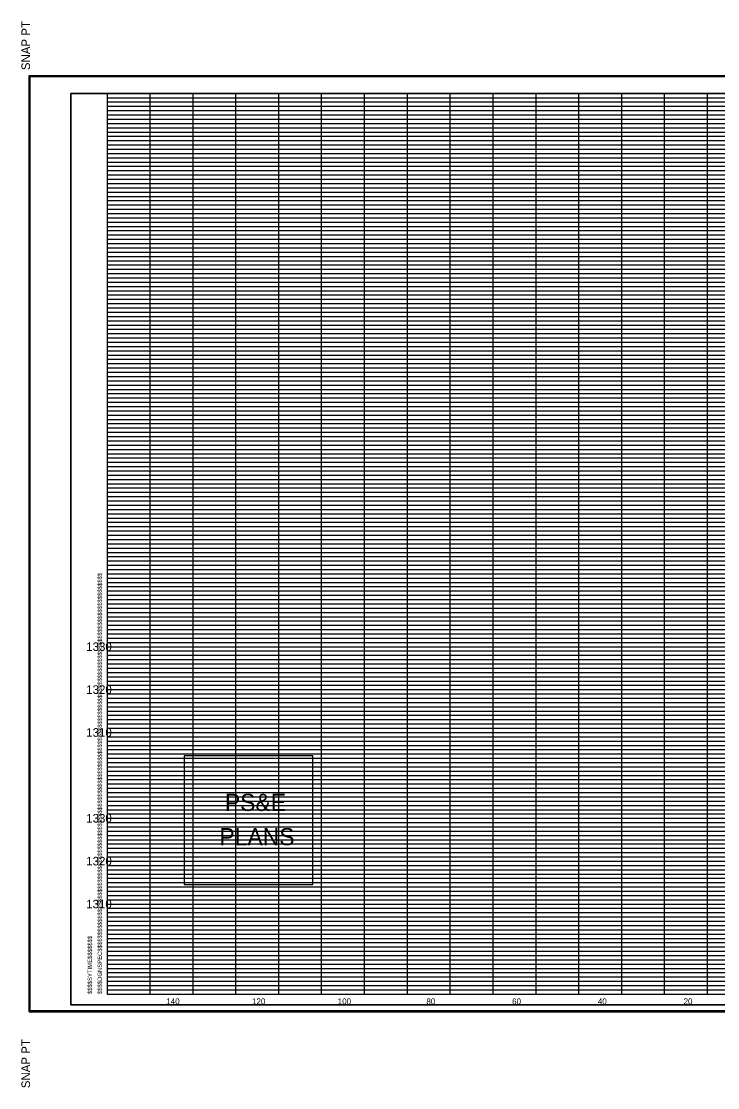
# Model space of a CAD drawing. Extents: x 980 to 1324, y 978 to 1497.
# Drawn here: x 979.9 to 1142.4, y 1248.2 to 1496.8 of the extents above; entities that cross this region are included whole.
import ezdxf

# ---------------------------------------------------------------- set-up
doc = ezdxf.new("R2010")
doc.units = 0
for name, color, linetype in [('DESIGN - SHEET - Corner Text', 7, 'Continuous'), ('DESIGN - SHEET - Light Grid', 7, 'Continuous'), ('DESIGN - SHEET - Linework', 7, 'Continuous'), ('DESIGN - SHEET - Plot Shape', 7, 'Continuous'), ('DESIGN - TYPICAL - Finished Grade and Subgrade', 7, 'Continuous'), ('DESIGN - TYPICAL - Text', 7, 'Continuous')]:
    doc.layers.add(name, color=color, linetype=linetype)

# ---------------------------------------------------------------- blocks, each defined once
blk = doc.blocks.new('XSTSHT')
at = {"layer": 'DESIGN - SHEET - Light Grid'}
for p, q in [((0, 20.9), (8, 20.9)), ((8, 20.9), (16, 20.9)), ((0, 20.8), (8, 20.8)), ((0, 20.7), (8, 20.7)), ((8, 20.8), (16, 20.8)), ((8, 20.7), (16, 20.7)), ((0, 20.6), (8, 20.6)), ((0, 20.5), (8, 20.5)), ((0, 20.4), (8, 20.4)), ((8, 20.6), (16, 20.6)), ((8, 20.5), (16, 20.5)), ((8, 20.4), (16, 20.4)), ((0, 20.3), (8, 20.3)), ((0, 20.2), (8, 20.2)), ((8, 20.3), (16, 20.3)), ((8, 20.2), (16, 20.2)), ((0, 20.1), (8, 20.1)), ((0, 19.9), (8, 19.9)), ((8, 20.1), (16, 20.1)), ((8, 19.9), (16, 19.9)), ((0, 19.8), (8, 19.8)), ((0, 19.7), (8, 19.7)), ((8, 19.8), (16, 19.8)), ((8, 19.7), (16, 19.7)), ((0, 19.6), (8, 19.6)), ((0, 19.5), (8, 19.5)), ((0, 19.4), (8, 19.4)), ((8, 19.6), (16, 19.6)), ((8, 19.5), (16, 19.5)), ((8, 19.4), (16, 19.4)), ((0, 19.3), (8, 19.3)), ((0, 19.2), (8, 19.2)), ((8, 19.3), (16, 19.3)), ((8, 19.2), (16, 19.2)), ((0, 19.1), (8, 19.1)), ((0, 18.9), (8, 18.9)), ((8, 19.1), (16, 19.1)), ((8, 18.9), (16, 18.9)), ((0, 18.8), (8, 18.8)), ((0, 18.7), (8, 18.7)), ((8, 18.8), (16, 18.8)), ((8, 18.7), (16, 18.7)), ((0, 18.6), (8, 18.6)), ((0, 18.5), (8, 18.5)), ((0, 18.4), (8, 18.4)), ((8, 18.6), (16, 18.6)), ((8, 18.5), (16, 18.5)), ((8, 18.4), (16, 18.4)), ((0, 18.3), (8, 18.3)), ((0, 18.2), (8, 18.2)), ((8, 18.3), (16, 18.3)), ((8, 18.2), (16, 18.2)), ((0, 18.1), (8, 18.1)), ((8, 18.1), (16, 18.1)), ((0, 17.9), (8, 17.9)), ((0, 17.8), (8, 17.8)), ((0, 17.7), (8, 17.7)), ((8, 17.9), (16, 17.9)), ((8, 17.8), (16, 17.8)), ((8, 17.7), (16, 17.7)), ((0, 17.6), (8, 17.6)), ((0, 17.5), (8, 17.5)), ((8, 17.6), (16, 17.6)), ((8, 17.5), (16, 17.5)), ((0, 17.4), (8, 17.4)), ((0, 17.3), (8, 17.3)), ((0, 17.2), (8, 17.2)), ((8, 17.4), (16, 17.4)), ((8, 17.3), (16, 17.3)), ((8, 17.2), (16, 17.2)), ((0, 17.1), (8, 17.1)), ((8, 17.1), (16, 17.1)), ((0, 16.9), (8, 16.9)), ((0, 16.8), (8, 16.8)), ((0, 16.7), (8, 16.7)), ((8, 16.9), (16, 16.9)), ((8, 16.8), (16, 16.8)), ((8, 16.7), (16, 16.7)), ((0, 16.6), (8, 16.6)), ((0, 16.5), (8, 16.5)), ((8, 16.6), (16, 16.6)), ((8, 16.5), (16, 16.5)), ((0, 16.4), (8, 16.4)), ((0, 16.3), (8, 16.3)), ((0, 16.2), (8, 16.2)), ((8, 16.4), (16, 16.4)), ((8, 16.3), (16, 16.3)), ((8, 16.2), (16, 16.2)), ((0, 16.1), (8, 16.1)), ((8, 16.1), (16, 16.1)), ((0, 15.9), (8, 15.9)), ((0, 15.8), (8, 15.8)), ((0, 15.7), (8, 15.7)), ((8, 15.9), (16, 15.9)), ((8, 15.8), (16, 15.8)), ((8, 15.7), (16, 15.7)), ((0, 15.6), (8, 15.6)), ((0, 15.5), (8, 15.5)), ((8, 15.6), (16, 15.6)), ((8, 15.5), (16, 15.5)), ((0, 15.4), (8, 15.4)), ((0, 15.3), (8, 15.3)), ((0, 15.2), (8, 15.2)), ((8, 15.4), (16, 15.4)), ((8, 15.3), (16, 15.3)), ((8, 15.2), (16, 15.2)), ((0, 15.1), (8, 15.1)), ((8, 15.1), (16, 15.1)), ((0, 14.9), (8, 14.9)), ((0, 14.8), (8, 14.8)), ((0, 14.7), (8, 14.7)), ((8, 14.9), (16, 14.9)), ((8, 14.8), (16, 14.8)), ((8, 14.7), (16, 14.7)), ((0, 14.6), (8, 14.6)), ((0, 14.5), (8, 14.5)), ((8, 14.6), (16, 14.6)), ((8, 14.5), (16, 14.5)), ((0, 14.4), (8, 14.4)), ((0, 14.3), (8, 14.3)), ((0, 14.2), (8, 14.2)), ((8, 14.4), (16, 14.4)), ((8, 14.3), (16, 14.3)), ((8, 14.2), (16, 14.2)), ((0, 14.1), (8, 14.1)), ((8, 14.1), (16, 14.1)), ((0, 13.9), (8, 13.9)), ((0, 13.8), (8, 13.8)), ((0, 13.7), (8, 13.7)), ((8, 13.9), (16, 13.9)), ((8, 13.8), (16, 13.8)), ((8, 13.7), (16, 13.7)), ((0, 13.6), (8, 13.6)), ((0, 13.5), (8, 13.5)), ((8, 13.6), (16, 13.6)), ((8, 13.5), (16, 13.5)), ((0, 13.4), (8, 13.4)), ((0, 13.3), (8, 13.3)), ((0, 13.2), (8, 13.2)), ((8, 13.4), (16, 13.4)), ((8, 13.3), (16, 13.3)), ((8, 13.2), (16, 13.2)), ((0, 13.1), (8, 13.1)), ((8, 13.1), (16, 13.1)), ((0, 12.9), (8, 12.9)), ((0, 12.8), (8, 12.8)), ((0, 12.7), (8, 12.7)), ((8, 12.9), (16, 12.9)), ((8, 12.8), (16, 12.8)), ((8, 12.7), (16, 12.7)), ((0, 12.6), (8, 12.6)), ((0, 12.5), (8, 12.5)), ((8, 12.6), (16, 12.6)), ((8, 12.5), (16, 12.5)), ((0, 12.4), (8, 12.4)), ((0, 12.3), (8, 12.3)), ((0, 12.2), (8, 12.2)), ((8, 12.4), (16, 12.4)), ((8, 12.3), (16, 12.3)), ((8, 12.2), (16, 12.2)), ((0, 12.1), (8, 12.1)), ((8, 12.1), (16, 12.1)), ((0, 11.9), (8, 11.9)), ((0, 11.8), (8, 11.8)), ((0, 11.7), (8, 11.7)), ((8, 11.9), (16, 11.9)), ((8, 11.8), (16, 11.8)), ((8, 11.7), (16, 11.7)), ((0, 11.6), (8, 11.6)), ((0, 11.5), (8, 11.5)), ((8, 11.6), (16, 11.6)), ((8, 11.5), (16, 11.5)), ((0, 11.4), (8, 11.4)), ((0, 11.3), (8, 11.3)), ((0, 11.2), (8, 11.2)), ((8, 11.4), (16, 11.4)), ((8, 11.3), (16, 11.3)), ((8, 11.2), (16, 11.2)), ((0, 11.1), (8, 11.1)), ((8, 11.1), (16, 11.1)), ((0, 10.9), (8, 10.9)), ((0, 10.8), (8, 10.8)), ((0, 10.7), (8, 10.7)), ((8, 10.9), (16, 10.9)), ((8, 10.8), (16, 10.8)), ((8, 10.7), (16, 10.7)), ((0, 10.6), (8, 10.6)), ((0, 10.5), (8, 10.5)), ((8, 10.6), (16, 10.6)), ((8, 10.5), (16, 10.5)), ((0, 10.4), (8, 10.4)), ((0, 10.3), (8, 10.3)), ((0, 10.2), (8, 10.2)), ((8, 10.4), (16, 10.4)), ((8, 10.3), (16, 10.3)), ((8, 10.2), (16, 10.2)), ((0, 10.1), (8, 10.1)), ((8, 10.1), (16, 10.1)), ((0, 9.9), (8, 9.9)), ((0, 9.8), (8, 9.8)), ((0, 9.7), (8, 9.7)), ((8, 9.9), (16, 9.9)), ((8, 9.8), (16, 9.8)), ((8, 9.7), (16, 9.7)), ((0, 9.6), (8, 9.6)), ((0, 9.5), (8, 9.5)), ((8, 9.6), (16, 9.6)), ((8, 9.5), (16, 9.5)), ((0, 9.4), (8, 9.4)), ((0, 9.3), (8, 9.3)), ((0, 9.2), (8, 9.2)), ((8, 9.4), (16, 9.4)), ((8, 9.3), (16, 9.3)), ((8, 9.2), (16, 9.2)), ((0, 9.1), (8, 9.1)), ((8, 9.1), (16, 9.1)), ((0, 8.9), (8, 8.9)), ((0, 8.8), (8, 8.8)), ((8, 8.9), (16, 8.9)), ((8, 8.8), (16, 8.8)), ((0, 8.7), (8, 8.7)), ((0, 8.6), (8, 8.6)), ((0, 8.5), (8, 8.5)), ((8, 8.7), (16, 8.7)), ((8, 8.6), (16, 8.6)), ((8, 8.5), (16, 8.5)), ((0, 8.4), (8, 8.4)), ((0, 8.3), (8, 8.3)), ((8, 8.4), (16, 8.4)), ((8, 8.3), (16, 8.3)), ((0, 8.2), (8, 8.2)), ((0, 8.1), (8, 8.1)), ((8, 8.2), (16, 8.2)), ((8, 8.1), (16, 8.1)), ((0, 7.9), (8, 7.9)), ((0, 7.8), (8, 7.8)), ((8, 7.9), (16, 7.9)), ((8, 7.8), (16, 7.8)), ((0, 7.7), (8, 7.7)), ((0, 7.6), (8, 7.6)), ((0, 7.5), (8, 7.5)), ((8, 7.7), (16, 7.7)), ((8, 7.6), (16, 7.6)), ((8, 7.5), (16, 7.5)), ((0, 7.4), (8, 7.4)), ((0, 7.3), (8, 7.3)), ((8, 7.4), (16, 7.4)), ((8, 7.3), (16, 7.3)), ((0, 7.2), (8, 7.2)), ((0, 7.1), (8, 7.1)), ((8, 7.2), (16, 7.2)), ((8, 7.1), (16, 7.1)), ((0, 6.9), (8, 6.9)), ((0, 6.8), (8, 6.8)), ((8, 6.9), (16, 6.9)), ((8, 6.8), (16, 6.8)), ((0, 6.7), (8, 6.7)), ((0, 6.6), (8, 6.6)), ((0, 6.5), (8, 6.5)), ((8, 6.7), (16, 6.7)), ((8, 6.6), (16, 6.6)), ((8, 6.5), (16, 6.5)), ((0, 6.4), (8, 6.4)), ((0, 6.3), (8, 6.3)), ((8, 6.4), (16, 6.4)), ((8, 6.3), (16, 6.3)), ((0, 6.2), (8, 6.2)), ((0, 6.1), (8, 6.1)), ((8, 6.2), (16, 6.2)), ((8, 6.1), (16, 6.1)), ((0, 5.9), (8, 5.9)), ((0, 5.8), (8, 5.8)), ((8, 5.9), (16, 5.9)), ((8, 5.8), (16, 5.8)), ((0, 5.7), (8, 5.7)), ((0, 5.6), (8, 5.6)), ((0, 5.5), (8, 5.5)), ((8, 5.7), (16, 5.7)), ((8, 5.6), (16, 5.6)), ((8, 5.5), (16, 5.5)), ((0, 5.4), (8, 5.4)), ((0, 5.3), (8, 5.3)), ((8, 5.4), (16, 5.4)), ((8, 5.3), (16, 5.3)), ((0, 5.2), (8, 5.2)), ((0, 5.1), (8, 5.1)), ((8, 5.2), (16, 5.2)), ((8, 5.1), (16, 5.1)), ((0, 4.9), (8, 4.9)), ((0, 4.8), (8, 4.8)), ((8, 4.9), (16, 4.9)), ((8, 4.8), (16, 4.8)), ((0, 4.7), (8, 4.7)), ((0, 4.6), (8, 4.6)), ((0, 4.5), (8, 4.5)), ((8, 4.7), (16, 4.7)), ((8, 4.6), (16, 4.6)), ((8, 4.5), (16, 4.5)), ((0, 4.4), (8, 4.4)), ((0, 4.3), (8, 4.3)), ((8, 4.4), (16, 4.4)), ((8, 4.3), (16, 4.3)), ((0, 4.2), (8, 4.2)), ((0, 4.1), (8, 4.1)), ((8, 4.2), (16, 4.2)), ((8, 4.1), (16, 4.1)), ((0, 3.9), (8, 3.9)), ((0, 3.8), (8, 3.8)), ((8, 3.9), (16, 3.9)), ((8, 3.8), (16, 3.8)), ((0, 3.7), (8, 3.7)), ((0, 3.6), (8, 3.6)), ((0, 3.5), (8, 3.5)), ((8, 3.7), (16, 3.7)), ((8, 3.6), (16, 3.6)), ((8, 3.5), (16, 3.5)), ((0, 3.4), (8, 3.4)), ((0, 3.3), (8, 3.3)), ((8, 3.4), (16, 3.4)), ((8, 3.3), (16, 3.3)), ((0, 3.2), (8, 3.2)), ((0, 3.1), (8, 3.1)), ((8, 3.2), (16, 3.2)), ((8, 3.1), (16, 3.1)), ((0, 2.9), (8, 2.9)), ((0, 2.8), (8, 2.8)), ((8, 2.9), (16, 2.9)), ((8, 2.8), (16, 2.8)), ((0, 2.7), (8, 2.7)), ((0, 2.6), (8, 2.6)), ((0, 2.5), (8, 2.5)), ((8, 2.7), (16, 2.7)), ((8, 2.6), (16, 2.6)), ((8, 2.5), (16, 2.5)), ((0, 2.4), (8, 2.4)), ((0, 2.3), (8, 2.3)), ((8, 2.4), (16, 2.4)), ((8, 2.3), (16, 2.3)), ((0, 2.2), (8, 2.2)), ((0, 2.1), (8, 2.1)), ((8, 2.2), (16, 2.2)), ((8, 2.1), (16, 2.1)), ((0, 1.9), (8, 1.9)), ((0, 1.8), (8, 1.8)), ((8, 1.9), (16, 1.9)), ((8, 1.8), (16, 1.8)), ((0, 1.7), (8, 1.7)), ((0, 1.6), (8, 1.6)), ((0, 1.5), (8, 1.5)), ((8, 1.7), (16, 1.7)), ((8, 1.6), (16, 1.6)), ((8, 1.5), (16, 1.5)), ((0, 1.4), (8, 1.4)), ((0, 1.3), (8, 1.3)), ((8, 1.4), (16, 1.4)), ((8, 1.3), (16, 1.3)), ((0, 1.2), (8, 1.2)), ((0, 1.1), (8, 1.1)), ((8, 1.2), (16, 1.2)), ((8, 1.1), (16, 1.1)), ((0, 0.9), (8, 0.9)), ((0, 0.8), (8, 0.8)), ((8, 0.9), (16, 0.9)), ((8, 0.8), (16, 0.8)), ((0, 0.7), (8, 0.7)), ((0, 0.6), (8, 0.6)), ((0, 0.5), (8, 0.5)), ((8, 0.7), (16, 0.7)), ((8, 0.6), (16, 0.6)), ((8, 0.5), (16, 0.5)), ((0, 0.4), (8, 0.4)), ((0, 0.3), (8, 0.3)), ((8, 0.4), (16, 0.4)), ((8, 0.3), (16, 0.3)), ((0, 0.2), (8, 0.2)), ((0, 0.1), (8, 0.1)), ((8, 0.2), (16, 0.2)), ((8, 0.1), (16, 0.1))]:
    blk.add_line(p, q, dxfattribs=at)
at = {"layer": 'DESIGN - SHEET - Linework'}
for p, q in [((-1.823, -0.414), (-1.823, 21.414)), ((-1.823, 21.414), (32.217, 21.414)), ((1, 0), (1, 21)), ((2, 0), (2, 21)), ((3, 0), (3, 21)), ((4, 0), (4, 21)), ((5, 0), (5, 21)), ((6, 0), (6, 21)), ((7, 0), (7, 21)), ((8, 0), (8, 21)), ((9, 0), (9, 21)), ((10, 0), (10, 21)), ((11, 0), (11, 21)), ((12, 0), (12, 21)), ((13, 0), (13, 21)), ((14, 0), (14, 21)), ((0, 20), (28, 20)), ((0, 19), (32, 19)), ((0, 18), (32, 18)), ((0, 17), (32, 17)), ((0, 16), (32, 16)), ((0, 15), (32, 15)), ((0, 14), (32, 14)), ((0, 13), (32, 13)), ((0, 12), (32, 12)), ((0, 11), (32, 11)), ((0, 10), (32, 10)), ((0, 9), (32, 9)), ((0, 8), (32, 8)), ((0, 7), (32, 7)), ((0, 6), (32, 6)), ((0, 5), (32, 5)), ((0, 4), (32, 4)), ((0, 3), (32, 3)), ((0, 2), (32, 2)), ((0, 1), (32, 1)), ((-1.823, -0.414), (32.217, -0.414))]:
    blk.add_line(p, q, dxfattribs=at)
blk.add_lwpolyline([(0, 21), (0, 0), (32, 0), (32, 21), (0, 21)], dxfattribs=at)
at = {"layer": 'DESIGN - SHEET - Plot Shape'}
for points in [[(-1.803, 21.394), (32.197, 21.394), (32.197, -0.394), (-1.803, -0.394)], [(-0.85, 21), (32, 21), (32, -0.25), (-0.85, -0.25)]]:
    blk.add_lwpolyline(points, close=True, dxfattribs=at)
at = {"layer": 'DESIGN - SHEET - Corner Text'}
for s, height, p in [('  SNAP PT', 0.2, (-1.803, 21.394)), ('$$$$DGNSPEC$$$$$$$$$$$$$$$$$$$$$$$$$$$$$$$$$$$$$$$$$$$$$$$$$$$$$$$$$$$$$$$$$$$$$$$$$$$$$$$$$$$$$$$$$$$$$$$$$$$$$$$$$$$$$$$$$$$', 0.100002, (-0.126, 0)), ('$$$$SYTIME$$$$$$$', 0.1, (-0.358, 0)), ('SNAP PT  ', 0.2, (-1.803, -2.194))]:
    blk.add_text(s, height=height, rotation=90, dxfattribs=at).set_placement(p)

msp = doc.modelspace()

# ---------------------------------------------------------------- linework, layer by layer
at = {"layer": 'DESIGN - SHEET - Corner Text'}
msp.add_lwpolyline([(1017.91, 1325.52), (1017.91, 1295.52), (1047.91, 1295.52), (1047.91, 1325.52)], close=True, dxfattribs=at)
at = {"layer": 'DESIGN - SHEET - Plot Shape'}
msp.add_lwpolyline([(991.5, 1267.5), (1320, 1267.5), (1320, 1480), (991.5, 1480)], close=True, dxfattribs=at)

# ---------------------------------------------------------------- block references
at = {"layer": 'DESIGN - TYPICAL - Finished Grade and Subgrade', "xscale": 10, "yscale": 10}
msp.add_blockref('XSTSHT', (1000, 1270), dxfattribs=at)

# ---------------------------------------------------------------- texts
at = {"layer": 'DESIGN - SHEET - Corner Text'}
for s, p in [('PS&E', (1027.42, 1312.7)), ('PLANS', (1026.14, 1304.7))]:
    msp.add_text(s, height=4, dxfattribs=at).set_placement(p)
at = {"layer": 'DESIGN - TYPICAL - Text'}
for s, height, p in [('     1330     ', 2, (991.37, 1350)), ('     1320     ', 2, (991.37, 1340)), ('     1310     ', 2, (991.37, 1330)), ('     1330     ', 2, (991.37, 1310)), ('     1320     ', 2, (991.37, 1300)), ('     1310     ', 2, (991.37, 1290)), ('     140     ', 1.4, (1011.14, 1267.6)), ('     120     ', 1.4, (1031.14, 1267.6)), ('     100     ', 1.4, (1051.14, 1267.6)), ('     80     ', 1.4, (1071.82, 1267.6)), ('     60     ', 1.4, (1091.82, 1267.6)), ('     40     ', 1.4, (1111.82, 1267.6)), ('     20     ', 1.4, (1131.82, 1267.6))]:
    msp.add_text(s, height=height, dxfattribs=at).set_placement(p)

doc.saveas('drawing.dxf')
